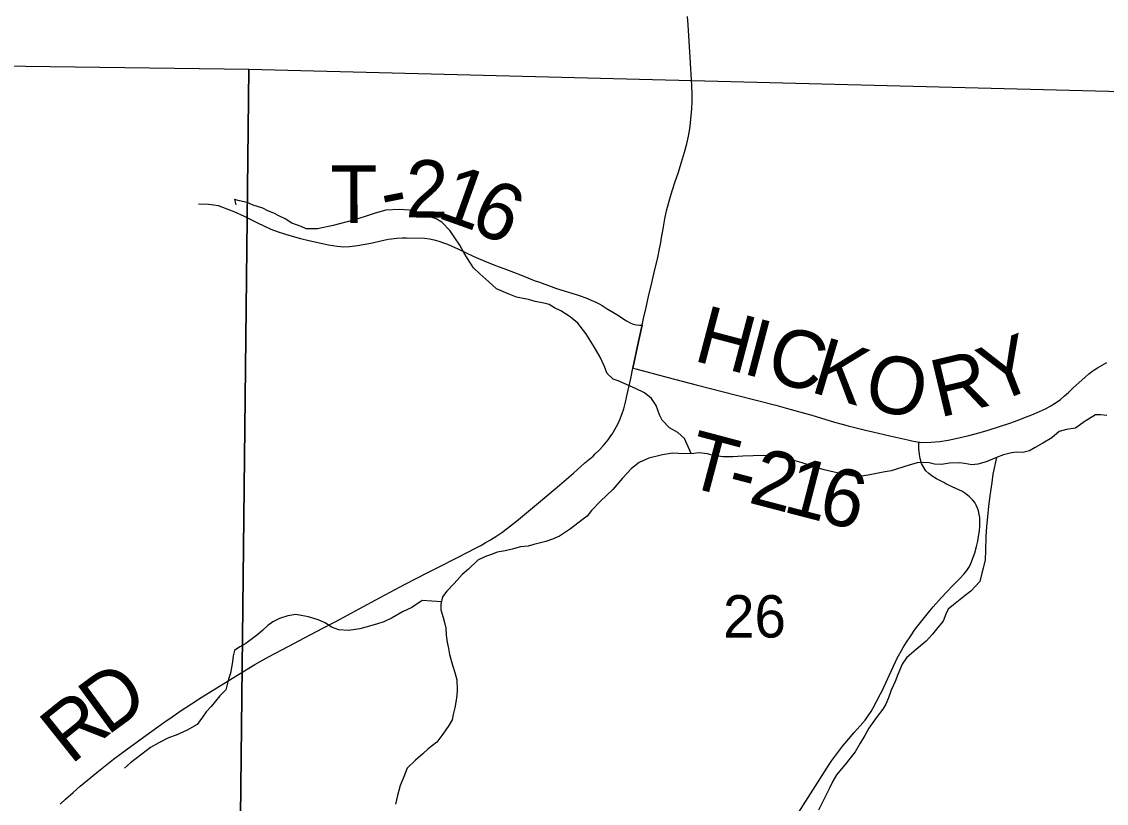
# Model space of a CAD drawing. Extents: x 0 to 34, y 0 to 22.
# Drawn here: x 4.314 to 5.387, y 16.248 to 17.021 of the extents above; entities that cross this region are included whole.
import ezdxf

# ---------------------------------------------------------------- set-up
doc = ezdxf.new("R2010")
doc.units = 0
for name, color, linetype in [('GM_X_Corporation', 7, 'Continuous'), ('GM_X_County_Road_Text', 7, 'Continuous'), ('GM_X_Interstate_Route', 7, 'Continuous'), ('GM_X_Major_Lake', 7, 'Continuous'), ('GM_X_Minor_Lake', 7, 'Continuous'), ('GM_X_Section', 7, 'Continuous'), ('GM_X_Township_Road_Text', 7, 'Continuous')]:
    doc.layers.add(name, color=color, linetype=linetype)

msp = doc.modelspace()

# ---------------------------------------------------------------- linework, layer by layer
at = {"layer": 'GM_X_Corporation'}
for points in [[(4.9278, 16.7208), (4.9293, 16.7273), (4.9315, 16.737), (4.9342, 16.749), (4.9374, 16.7625), (4.9395, 16.7716), (4.9434, 16.7876), (4.9451, 16.7961), (4.9462, 16.8024), (4.9469, 16.8069), (4.9485, 16.8159), (4.9503, 16.8259), (4.952, 16.8336), (4.9539, 16.841), (4.9559, 16.848), (4.9576, 16.8536), (4.9605, 16.8627), (4.9634, 16.8711), (4.9668, 16.882), (4.9696, 16.8918), (4.9719, 16.9), (4.9736, 16.9074), (4.9749, 16.9147), (4.9757, 16.9209), (4.9764, 16.928), (4.9769, 16.9344), (4.9772, 16.9422), (4.9773, 16.9489), (4.9769, 16.9578), (4.9753, 16.9853), (4.9733, 17.0175), (4.9728, 17.0257)], [(4.9187, 16.6782), (4.9243, 16.7045), (4.9269, 16.7166), (4.9278, 16.7208)], [(4.3523, 16.2473), (4.3577, 16.2522), (4.3652, 16.2589), (4.3722, 16.265), (4.3793, 16.2709), (4.3887, 16.2787), (4.3967, 16.2851), (4.4052, 16.2916), (4.4126, 16.2972), (4.4312, 16.3108), (4.455, 16.3279), (4.463, 16.3335), (4.4721, 16.3398), (4.4823, 16.3466), (4.4919, 16.3526), (4.5071, 16.3621), (4.5185, 16.3692), (4.5288, 16.3756), (4.5448, 16.3854), (4.5584, 16.3929), (4.5785, 16.4036), (4.5941, 16.4118), (4.612, 16.4211), (4.6243, 16.4276), (4.6371, 16.4343), (4.6479, 16.4402), (4.6689, 16.4514), (4.6936, 16.4646), (4.7152, 16.4759), (4.7244, 16.4806), (4.7465, 16.4918), (4.7638, 16.5006), (4.7683, 16.5031), (4.7725, 16.5055), (4.778, 16.5087), (4.7832, 16.5119), (4.7891, 16.5159), (4.7947, 16.5201), (4.8035, 16.5271), (4.8214, 16.5419), (4.8356, 16.5538), (4.846, 16.5627), (4.8598, 16.5746), (4.8713, 16.5845), (4.8794, 16.5914), (4.8815, 16.5934), (4.8854, 16.5971), (4.8894, 16.6015), (4.891, 16.6034), (4.8941, 16.6074), (4.897, 16.6112), (4.8982, 16.613), (4.9026, 16.6206), (4.904, 16.6235), (4.9061, 16.6283), (4.908, 16.6333), (4.9096, 16.6382), (4.9114, 16.6447), (4.9124, 16.6493), (4.9137, 16.6551), (4.9165, 16.668), (4.9187, 16.6782)]]:
    msp.add_lwpolyline(points, dxfattribs=at)
at = {"layer": 'GM_X_Interstate_Route'}
for points in [[(4.4891, 16.8407), (4.499, 16.8404), (4.5043, 16.8398), (4.5086, 16.8389), (4.5128, 16.8375), (4.524, 16.833), (4.5342, 16.8284), (4.5474, 16.8219), (4.5538, 16.8188), (4.5605, 16.8156), (4.5669, 16.8132), (4.575, 16.8107), (4.5817, 16.8088), (4.5899, 16.8065), (4.5983, 16.8045), (4.6177, 16.8003), (4.6261, 16.7989), (4.6328, 16.7983), (4.6384, 16.7986), (4.6463, 16.7996), (4.6594, 16.8019), (4.6767, 16.8057), (4.6799, 16.8062), (4.6852, 16.8066), (4.6904, 16.8069), (4.6949, 16.8071), (4.7126, 16.8067), (4.7175, 16.8061), (4.7221, 16.8051), (4.7269, 16.8038), (4.7314, 16.8022), (4.7352, 16.8008), (4.739, 16.7992), (4.7456, 16.7961), (4.7531, 16.7925), (4.7615, 16.7886), (4.7659, 16.7866), (4.7762, 16.7824), (4.7839, 16.7794), (4.7938, 16.7756), (4.8076, 16.7704), (4.8212, 16.765), (4.8263, 16.7631), (4.8379, 16.7589), (4.8431, 16.7571), (4.8625, 16.751), (4.8666, 16.7497), (4.8722, 16.7476), (4.8775, 16.7454), (4.8821, 16.7434), (4.8853, 16.7418), (4.8883, 16.7401), (4.8934, 16.737), (4.8994, 16.7334), (4.9043, 16.7303), (4.9089, 16.7274), (4.9125, 16.7251), (4.9159, 16.7231), (4.9191, 16.7218), (4.9221, 16.721), (4.9251, 16.7207), (4.9278, 16.7208)], [(4.9278, 16.7208), (4.9269, 16.7166), (4.9243, 16.7045), (4.9187, 16.6782)], [(4.9187, 16.6782), (4.9217, 16.6775), (4.9535, 16.6689), (4.9813, 16.6617), (5.021, 16.6515), (5.0601, 16.6415), (5.0716, 16.6384), (5.0956, 16.6317), (5.118, 16.625), (5.1256, 16.6229), (5.1316, 16.6212), (5.142, 16.6185), (5.1486, 16.6169), (5.1559, 16.6152), (5.1728, 16.6114), (5.1904, 16.6074), (5.1944, 16.6065), (5.1998, 16.6054), (5.2014, 16.6051), (5.2025, 16.605), (5.2036, 16.6049), (5.2134, 16.6052), (5.2222, 16.6059), (5.2304, 16.6072), (5.2441, 16.61), (5.2509, 16.6116), (5.2621, 16.6146), (5.27, 16.6169), (5.2915, 16.6239), (5.2998, 16.6269), (5.3054, 16.629), (5.3131, 16.6322), (5.3207, 16.6354), (5.3268, 16.6382), (5.3319, 16.641), (5.3364, 16.6438), (5.3416, 16.6473), (5.3456, 16.6508), (5.3495, 16.6542), (5.3537, 16.6584), (5.3658, 16.6695), (5.3695, 16.6727), (5.3725, 16.675), (5.3754, 16.677), (5.3781, 16.6786), (5.3873, 16.6837)], [(5.0757, 16.2286), (5.1129, 16.2866), (5.1154, 16.2903), (5.1194, 16.2958), (5.1263, 16.305), (5.1321, 16.3118), (5.1376, 16.3181), (5.1434, 16.3248), (5.1484, 16.3304), (5.1497, 16.3322), (5.1544, 16.339), (5.156, 16.3417), (5.1636, 16.3562), (5.1648, 16.3587), (5.1783, 16.388), (5.1798, 16.3909), (5.1861, 16.4022), (5.1892, 16.4073), (5.1928, 16.4128), (5.1979, 16.4201), (5.2124, 16.4384), (5.2155, 16.4422), (5.2237, 16.4515), (5.229, 16.457), (5.2355, 16.4636), (5.2421, 16.4703), (5.2463, 16.4749), (5.2489, 16.4783), (5.2514, 16.4823), (5.2529, 16.4852), (5.2545, 16.4893), (5.2567, 16.4958), (5.2585, 16.5018), (5.2597, 16.5071), (5.2606, 16.5118), (5.2613, 16.5175), (5.2616, 16.5222), (5.2618, 16.5267), (5.2616, 16.5306), (5.2611, 16.5337), (5.2604, 16.5371), (5.2595, 16.54), (5.2582, 16.5429), (5.2568, 16.5453), (5.2549, 16.5479), (5.2517, 16.5511), (5.2478, 16.554), (5.2468, 16.5547), (5.2438, 16.5565), (5.2386, 16.5591), (5.2283, 16.564), (5.226, 16.5652), (5.2189, 16.5689), (5.2145, 16.5715), (5.2112, 16.574), (5.2085, 16.5769), (5.2063, 16.5802), (5.2042, 16.5841), (5.2028, 16.5891), (5.2021, 16.593), (5.2018, 16.5957), (5.2016, 16.5988), (5.2014, 16.6019), (5.2014, 16.6051)]]:
    msp.add_lwpolyline(points, dxfattribs=at)
at = {"layer": 'GM_X_Minor_Lake'}
for points in [[(3.7042, 16.9849), (4.539, 16.9739), (4.5275, 15.9394), (3.6897, 15.9465), (3.703, 16.8594)], [(4.539, 16.9739), (5.5566, 16.9477), (5.5393, 15.9226), (4.5275, 15.9394)]]:
    msp.add_lwpolyline(points, close=True, dxfattribs=at)
at = {"layer": 'GM_X_Township_Road_Text'}
for points in [[(4.9762, 16.5938), (4.9696, 16.6086), (4.963, 16.6146), (4.955, 16.6194), (4.9477, 16.6269), (4.945, 16.6322), (4.9418, 16.6413), (4.9372, 16.6481), (4.9303, 16.6537), (4.9211, 16.6581), (4.904, 16.6658), (4.8991, 16.6673), (4.8933, 16.6729), (4.8902, 16.6805), (4.8862, 16.6892), (4.8804, 16.6994), (4.8723, 16.7126), (4.8642, 16.7227), (4.8565, 16.7291), (4.8473, 16.735), (4.8412, 16.738), (4.8359, 16.7413), (4.8306, 16.7424), (4.8222, 16.7442), (4.8154, 16.746), (4.8101, 16.747), (4.8036, 16.7485), (4.7952, 16.7518), (4.7838, 16.7565), (4.7761, 16.7637), (4.7673, 16.7715), (4.7612, 16.7775), (4.755, 16.7866), (4.7515, 16.7926), (4.7476, 16.7998), (4.7426, 16.8069), (4.7379, 16.8141), (4.7298, 16.8224), (4.7241, 16.8257), (4.7173, 16.8283), (4.7093, 16.8312), (4.7024, 16.8334), (4.6975, 16.8344), (4.688, 16.835), (4.6744, 16.8345), (4.6638, 16.8316), (4.6548, 16.8285), (4.6424, 16.8245), (4.6224, 16.8192), (4.6069, 16.8159), (4.5955, 16.8161), (4.5906, 16.8184), (4.5814, 16.8216), (4.5749, 16.8257), (4.5685, 16.8287), (4.5635, 16.8313), (4.5578, 16.8338), (4.5528, 16.8364), (4.5433, 16.8393), (4.5372, 16.8419), (4.5296, 16.8437), (4.5247, 16.8448), (4.5259, 16.8398)], [(5.3872, 16.6315), (5.3811, 16.6322), (5.3762, 16.6321), (5.365, 16.6251), (5.3563, 16.6189), (5.3473, 16.6176), (5.3401, 16.6156), (5.333, 16.6094), (5.324, 16.604), (5.3165, 16.5997), (5.3109, 16.5965), (5.3044, 16.5949), (5.2984, 16.5952), (5.2931, 16.5947), (5.2852, 16.5927), (5.2784, 16.5899), (5.2679, 16.5856), (5.2599, 16.5832), (5.2539, 16.5827), (5.2467, 16.5841), (5.2417, 16.5848), (5.2319, 16.5843), (5.224, 16.583), (5.2168, 16.5833), (5.2118, 16.5848), (5.2062, 16.5851), (5.1997, 16.5846), (5.1918, 16.5822), (5.1741, 16.5766)], [(5.1741, 16.5766), (5.1662, 16.5753), (5.1514, 16.5724), (5.1446, 16.5716), (5.1371, 16.5715), (5.1295, 16.5729), (5.1177, 16.5754), (5.1078, 16.5779), (5.096, 16.5815), (5.0861, 16.5848), (5.0747, 16.5881), (5.0618, 16.5905), (5.0478, 16.5918), (5.0274, 16.5912), (5.0175, 16.5906), (5.0077, 16.5905), (4.9982, 16.5919), (4.9925, 16.5937), (4.9838, 16.5947), (4.9789, 16.5939), (4.9709, 16.5937), (4.9633, 16.594), (4.958, 16.5943), (4.9478, 16.5926), (4.9346, 16.5894), (4.9249, 16.5851), (4.9174, 16.5792), (4.9084, 16.5696), (4.8987, 16.5584), (4.8868, 16.5468), (4.8778, 16.5375), (4.8734, 16.5321), (4.8685, 16.5283), (4.8569, 16.5193), (4.846, 16.5123), (4.8393, 16.5092), (4.8325, 16.5068), (4.8208, 16.5039), (4.8151, 16.5023), (4.8076, 16.5015), (4.7993, 16.4994), (4.7925, 16.4978), (4.7845, 16.4962), (4.7789, 16.4942), (4.7729, 16.4922), (4.7653, 16.4886), (4.756, 16.4797), (4.75, 16.4743), (4.7418, 16.4655), (4.7347, 16.4577), (4.7303, 16.4523), (4.7289, 16.4451), (4.7289, 16.4394), (4.731, 16.4318), (4.7325, 16.4269), (4.7338, 16.4212), (4.7342, 16.4143), (4.7351, 16.4075), (4.7363, 16.401), (4.7372, 16.3953), (4.7403, 16.3847), (4.7427, 16.3775), (4.7447, 16.3703), (4.7449, 16.3604), (4.7446, 16.3547), (4.7435, 16.3482), (4.7425, 16.3425), (4.741, 16.336), (4.74, 16.3307), (4.7367, 16.3249), (4.7307, 16.3164), (4.7248, 16.3087), (4.7162, 16.3018), (4.7109, 16.2971), (4.7038, 16.2909), (4.6956, 16.2828), (4.6923, 16.2744), (4.6887, 16.2656), (4.6858, 16.256), (4.684, 16.2472)], [(5.2784, 16.5899), (5.2745, 16.5735), (5.2735, 16.5651), (5.2717, 16.5522), (5.2704, 16.5419), (5.2694, 16.5312), (5.2684, 16.5217), (5.2678, 16.5117), (5.2672, 16.498), (5.267, 16.4889), (5.2652, 16.4805), (5.2638, 16.4755), (5.2616, 16.4675), (5.2527, 16.4578), (5.2474, 16.4536), (5.2358, 16.4443), (5.2306, 16.44), (5.228, 16.435), (5.2255, 16.4281), (5.2203, 16.422), (5.215, 16.4154), (5.2087, 16.4085), (5.1967, 16.3984), (5.1893, 16.3918), (5.1848, 16.3856), (5.1808, 16.3753), (5.1779, 16.3684), (5.1742, 16.36), (5.1713, 16.3523), (5.1687, 16.3462), (5.1658, 16.3412), (5.1602, 16.3339), (5.152, 16.3223), (5.148, 16.315), (5.1435, 16.3074), (5.1384, 16.2989), (5.1287, 16.2866), (5.1201, 16.2762), (5.1164, 16.27), (5.1131, 16.2631), (5.1021, 16.2413)], [(4.7293, 16.4474), (4.7103, 16.4486), (4.7001, 16.4416), (4.6907, 16.4373), (4.6806, 16.4314), (4.6723, 16.4275), (4.6663, 16.4255), (4.6606, 16.4239), (4.6486, 16.4207), (4.6376, 16.419), (4.6278, 16.4196), (4.6205, 16.4221), (4.6144, 16.4266), (4.6076, 16.4296), (4.598, 16.4325), (4.5908, 16.4339), (4.5855, 16.4346), (4.5776, 16.4333), (4.5693, 16.4309), (4.5625, 16.4274), (4.5577, 16.4239), (4.5528, 16.4192), (4.5479, 16.415), (4.5412, 16.4099), (4.536, 16.406), (4.53, 16.4029), (4.5247, 16.399), (4.5233, 16.394), (4.5226, 16.3879), (4.5209, 16.3769), (4.5187, 16.3707), (4.5176, 16.3654), (4.5162, 16.3604), (4.5102, 16.3542), (4.5017, 16.3438), (4.4968, 16.3384), (4.4931, 16.3331), (4.4879, 16.3261), (4.4778, 16.3203), (4.4672, 16.3155), (4.4593, 16.3128), (4.4499, 16.308), (4.4417, 16.3033), (4.4331, 16.2967), (4.4218, 16.2882), (4.4158, 16.2828)]]:
    msp.add_lwpolyline(points, dxfattribs=at)

# ---------------------------------------------------------------- texts
at = {"layer": 'GM_X_County_Road_Text'}
msp.add_text('26', height=0.04186, rotation=0, dxfattribs=at).set_placement((5.0078, 16.412))
at = {"layer": 'GM_X_Major_Lake'}
for s, rotation, p in [('D', 36.2572, (4.3987, 16.3143)), ('R', 38.6702, (4.3628, 16.2855))]:
    msp.add_text(s, height=0.0568, rotation=rotation, dxfattribs=at).set_placement(p)
at = {"layer": 'GM_X_Section'}
for s, rotation, p in [('2', 359.2538, (4.6936, 16.8273)), ('T', 0.1421, (4.6197, 16.8218)), ('1', 340.3171, (4.7235, 16.8277)), ('6', 335.4659, (4.755, 16.8165)), ('-', 11.2075, (4.674, 16.8231)), ('H', 345.2561, (4.9773, 16.686)), ('I', 345.2405, (5.0256, 16.6733)), ('C', 344.7918, (5.0481, 16.6674)), ('Y', 21.433, (5.2753, 16.6426)), ('K', 343.3751, (5.0927, 16.6552)), ('O', 347.5106, (5.145, 16.6398)), ('R', 13.3735, (5.2216, 16.6292)), ('T', 345.1747, (4.9683, 16.5625)), ('2', 345.2642, (5.0317, 16.5457)), ('1', 345.4929, (5.0656, 16.5368)), ('-', 345.1994, (5.0093, 16.5516)), ('6', 346.0803, (5.0998, 16.5279))]:
    msp.add_text(s, height=0.0568, rotation=rotation, dxfattribs=at).set_placement(p)

doc.saveas('drawing.dxf')
